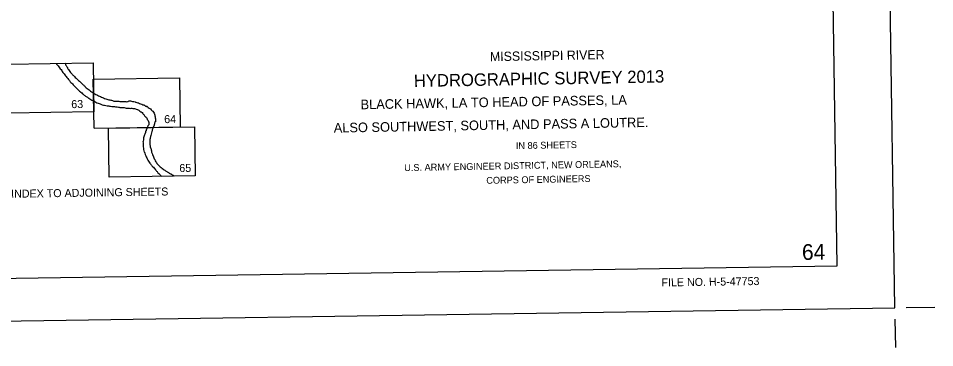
# Model space of a CAD drawing. Extents: x 3807117 to 3845308, y 337856 to 363736.
# Drawn here: x 3831918 to 3845308, y 338406 to 343219 of the extents above; entities that cross this region are included whole.
import ezdxf

# ---------------------------------------------------------------- set-up
doc = ezdxf.new("R2010")
doc.units = 0
for name, color, linetype in [('G-ANNO-NPLT', 7, 'Continuous'), ('V-ANNO-DIMS', 7, 'Continuous'), ('V-ANNO-NPLT', 7, 'Continuous'), ('V-ANNO-SYMB', 7, 'Continuous'), ('V-ANNO-TEXT', 7, 'Continuous')]:
    doc.layers.add(name, color=color, linetype=linetype)

msp = doc.modelspace()

# ---------------------------------------------------------------- linework, layer by layer
at = {"layer": 'G-ANNO-NPLT'}
msp.add_lwpolyline([(3808062, 338440), (3844725, 338989), (3844362, 363153), (3807700, 362604)], close=True, dxfattribs=at)
at = {"layer": 'V-ANNO-DIMS'}
for p, q in [((3844891, 338991), (3845308, 338998)), ((3844727, 338822), (3844733, 338406))]:
    msp.add_line(p, q, dxfattribs=at)
at = {"layer": 'V-ANNO-NPLT'}
for points in [[(3831765, 341833), (3831754, 342551), (3833010, 342569), (3833022, 341851)], [(3833025, 341612), (3833014, 342330), (3834271, 342350), (3834282, 341632)], [(3833022, 341851), (3831765, 341833)], [(3833025, 341612), (3834282, 341632)], [(3833246, 340897), (3833235, 341615), (3834492, 341635), (3834504, 340917)], [(3834504, 340917), (3833246, 340897)]]:
    msp.add_lwpolyline(points, dxfattribs=at)
for points in [[(3832469, 342561), (3832486, 342538), (3832510, 342509), (3832531, 342483), (3832552, 342454), (3832570, 342429), (3832588, 342406)], [(3832599, 342563), (3832605, 342550), (3832609, 342541), (3832622, 342518), (3832635, 342498), (3832641, 342483), (3832660, 342457), (3832680, 342429), (3832695, 342412)], [(3832588, 342406), (3832608, 342379), (3832629, 342354), (3832653, 342325), (3832677, 342293), (3832698, 342270), (3832718, 342249), (3832724, 342241)], [(3832695, 342412), (3832712, 342395), (3832725, 342381), (3832750, 342356), (3832777, 342332), (3832796, 342312), (3832825, 342287), (3832842, 342270)], [(3832842, 342270), (3832867, 342247), (3832896, 342218), (3832923, 342193), (3832954, 342172), (3832974, 342153)], [(3832724, 342241), (3832750, 342216), (3832774, 342191), (3832797, 342168), (3832826, 342144), (3832830, 342141)], [(3832830, 342141), (3832858, 342116), (3832891, 342089), (3832910, 342078), (3832947, 342052), (3832979, 342032), (3833005, 342017)], [(3832974, 342153), (3832999, 342138), (3833017, 342126)], [(3833017, 342126), (3833036, 342114), (3833063, 342100), (3833119, 342075), (3833177, 342049), (3833212, 342037), (3833240, 342028), (3833270, 342024), (3833280, 342022), (3833305, 342012), (3833322, 342009), (3833349, 342007)], [(3833005, 342017), (3833014, 342013), (3833019, 342011)], [(3833019, 342011), (3833035, 342003), (3833067, 341986), (3833101, 341972), (3833144, 341957), (3833179, 341948), (3833214, 341942), (3833264, 341934), (3833304, 341930), (3833340, 341926), (3833380, 341922)], [(3833349, 342007), (3833387, 342006), (3833415, 342003), (3833451, 342003), (3833488, 342002), (3833519, 342002), (3833525, 342006), (3833529, 342009), (3833551, 342011), (3833558, 342011), (3833587, 342003), (3833627, 341997), (3833631, 341995)], [(3833631, 341995), (3833664, 341984), (3833672, 341982), (3833705, 341969), (3833737, 341956), (3833745, 341952), (3833753, 341953), (3833759, 341950), (3833768, 341945), (3833777, 341936), (3833783, 341933), (3833788, 341932), (3833793, 341933), (3833796, 341934), (3833800, 341930), (3833831, 341907), (3833847, 341897), (3833868, 341871), (3833882, 341861), (3833901, 341833), (3833912, 341806), (3833917, 341779)], [(3833380, 341922), (3833399, 341917), (3833415, 341915), (3833446, 341915), (3833450, 341915), (3833479, 341910), (3833513, 341904), (3833539, 341904), (3833567, 341904), (3833571, 341906), (3833573, 341907), (3833578, 341906), (3833602, 341902), (3833629, 341897)], [(3833629, 341897), (3833653, 341888), (3833661, 341885), (3833678, 341875), (3833707, 341853), (3833714, 341850), (3833736, 341828), (3833764, 341795)], [(3833764, 341795), (3833779, 341776), (3833784, 341774), (3833789, 341771), (3833799, 341743), (3833804, 341735), (3833813, 341724), (3833823, 341695), (3833824, 341686), (3833823, 341663), (3833818, 341658), (3833811, 341648), (3833807, 341633), (3833802, 341624)], [(3833917, 341779), (3833920, 341748), (3833923, 341723), (3833923, 341713), (3833924, 341709), (3833923, 341708), (3833921, 341706), (3833918, 341705), (3833915, 341704), (3833913, 341701), (3833912, 341697), (3833901, 341653), (3833897, 341644), (3833892, 341634), (3833889, 341626)], [(3833802, 341624), (3833796, 341604), (3833792, 341597), (3833785, 341576), (3833783, 341573), (3833779, 341572), (3833776, 341570), (3833776, 341562), (3833769, 341536), (3833767, 341532), (3833765, 341528), (3833757, 341502), (3833754, 341494)], [(3833889, 341626), (3833884, 341612), (3833876, 341590), (3833868, 341563), (3833857, 341524), (3833849, 341493), (3833847, 341482)], [(3833754, 341494), (3833750, 341485), (3833746, 341461), (3833744, 341423), (3833744, 341419)], [(3833847, 341483), (3833843, 341458), (3833841, 341451), (3833839, 341420)], [(3833761, 341265), (3833753, 341304), (3833749, 341342), (3833746, 341376), (3833744, 341419)], [(3833839, 341420), (3833839, 341386), (3833843, 341358), (3833849, 341327), (3833852, 341322), (3833860, 341295), (3833866, 341265)], [(3833761, 341265), (3833773, 341230), (3833787, 341193), (3833801, 341163), (3833818, 341132)], [(3833866, 341265), (3833873, 341241), (3833886, 341209), (3833898, 341180), (3833911, 341154), (3833929, 341122)], [(3833818, 341132), (3833840, 341101), (3833870, 341062), (3833891, 341043)], [(3833891, 341043), (3833911, 341019), (3833932, 340993), (3833957, 340963)], [(3833929, 341122), (3833944, 341098), (3833969, 341070), (3833993, 341048)], [(3833993, 341048), (3834014, 341029), (3834021, 341024), (3834024, 341024), (3834025, 341023), (3834049, 341005), (3834070, 340991), (3834088, 340982), (3834101, 340972)], [(3833957, 340963), (3833981, 340939), (3834012, 340909)], [(3834101, 340972), (3834122, 340958), (3834125, 340957), (3834143, 340946), (3834150, 340943), (3834152, 340943), (3834158, 340940), (3834179, 340925), (3834187, 340923), (3834202, 340913)]]:
    msp.add_spline(points, degree=3, dxfattribs=at)
at = {"layer": 'V-ANNO-SYMB'}
msp.add_lwpolyline([(3810802, 339106), (3843882, 339601), (3843539, 362515), (3810459, 362020), (3810802, 339106)], dxfattribs=at)

# ---------------------------------------------------------------- texts
at = {"layer": 'V-ANNO-NPLT'}
for s, height, p in [('63', 117, (3832692, 341906)), ('64', 117, (3834050, 341687)), ('65', 117, (3834271, 340972)), ('INDEX TO ADJOINING SHEETS', 116.66, (3831814, 340596))]:
    msp.add_text(s, height=height, rotation=0.8584, dxfattribs=at).set_placement(p)
at = {"layer": 'V-ANNO-TEXT'}
for s, height, rotation, p in [('MISSISSIPPI RIVER', 135, 1.0341, (3838810, 342592)), ('HYDROGRAPHIC SURVEY 2013', 181.7, 1.0341, (3837699, 342215)), ('BLACK HAWK, LA TO HEAD OF PASSES, LA', 140, 1.0341, (3836920, 341889)), ('ALSO SOUTHWEST, SOUTH, AND PASS A LOUTRE.', 140, 1.0341, (3836528, 341548)), ('IN 86 SHEETS', 100, 1.0341, (3839189, 341307)), ('U.S. ARMY ENGINEER DISTRICT, NEW ORLEANS,', 100, 1.0341, (3837558, 340986)), ('CORPS OF ENGINEERS', 100, 1.0341, (3838757, 340800)), ('64', 230, 0.8584, (3843370, 339687)), ('FILE NO. H-5-47753', 116.66, 0.8584, (3841317, 339300))]:
    msp.add_text(s, height=height, rotation=rotation, dxfattribs=at).set_placement(p)

doc.saveas('drawing.dxf')
